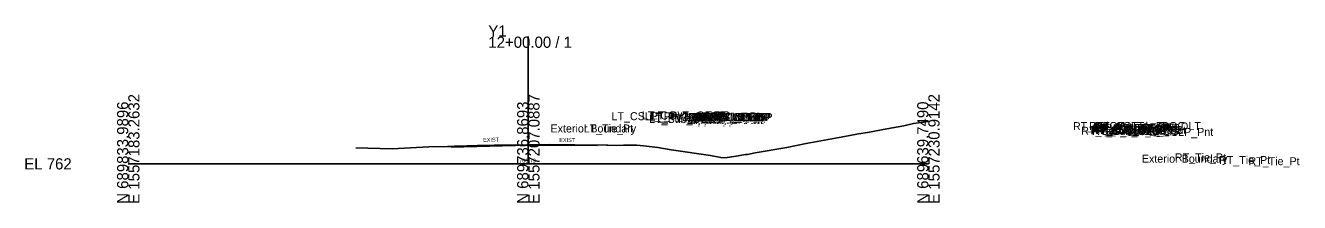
# Model space of a CAD drawing. Extents: x -26 to 303, y -10 to 5005.
# Drawn here: x -25.7 to 292.8, y 1990.3 to 2034.7 of the extents above; entities that cross this region are included whole.
import ezdxf

# ---------------------------------------------------------------- set-up
doc = ezdxf.new("R2010")
doc.units = 0
for name, color, linetype in [('Default', 7, 'Continuous'), ('Exist Cross Section Cell', 7, 'Continuous'), ('Exist XS Center Line Elevation Label', 7, 'Continuous'), ('Exist XS Ground Line', 7, 'Continuous'), ('Prop CMT Pvmt Course 1', 7, 'Continuous'), ('Prop CMT Pvmt Surface', 7, 'Continuous'), ('Prop XS SE Text', 7, 'Continuous')]:
    doc.layers.add(name, color=color, linetype=linetype)

msp = doc.modelspace()

# ---------------------------------------------------------------- linework, layer by layer
at = {"layer": 'Exist Cross Section Cell'}
for p, q in [((100, 2000), (100, 2031.86)), ((0, 2000), (100, 2000)), ((100, 2000), (200, 2000))]:
    msp.add_line(p, q, dxfattribs=at)
at = {"layer": 'Exist XS Ground Line'}
msp.add_lwpolyline([(56.85, 2003.98), (65.96, 2003.78), (75.1, 2004.22), (79.8, 2004.31), (80.39, 2004.31), (80.75, 2004.33), (81.54, 2004.42), (83.18, 2004.46), (83.69, 2004.47), (84.67, 2004.49), (85.59, 2004.52), (87.3, 2004.56), (91.45, 2004.65), (93.01, 2004.69), (94.36, 2004.71), (100, 2004.79), (105.33, 2004.86), (111.61, 2004.76), (119.57, 2004.66), (119.87, 2004.65), (122.02, 2004.63), (123.79, 2004.64), (127.09, 2004.72), (128.79, 2004.54), (132.4, 2004.13), (135.74, 2003.47), (145.55, 2002.05), (148.14, 2001.63), (149.12, 2001.48), (151.98, 2001.95), (154.26, 2002.33), (154.76, 2002.37), (156.71, 2002.75), (164.58, 2004.06), (169.43, 2005.08), (178.61, 2006.78), (182.51, 2007.5), (184.75, 2007.86), (189.65, 2008.78), (193.85, 2009.55), (196.32, 2010.07), (200, 2010.62)], dxfattribs=at)
at = {"layer": 'Prop CMT Pvmt Course 1'}
for p, q in [((80.75, 2004.21), (100, 2004.66)), ((80.75, 2004.33), (80.75, 2004.21)), ((100, 2004.66), (117.33, 2004.56)), ((117.33, 2004.69), (117.33, 2004.56))]:
    msp.add_line(p, q, dxfattribs=at)
for points in [[(100, 2004.79), (100, 2004.66)], [(100, 2004.66), (100, 2004.79)], [(100, 2004.79), (117.33, 2004.69)]]:
    msp.add_lwpolyline(points, dxfattribs=at)
at = {"layer": 'Prop CMT Pvmt Surface'}
msp.add_line((80.75, 2004.33), (100, 2004.79), dxfattribs=at)
msp.add_lwpolyline([(100, 2004.79), (117.33, 2004.69)], dxfattribs=at)

# ---------------------------------------------------------------- texts
at = {"layer": 'Default'}
for s, height, p in [('LT_CSLP_Pnt', 2, (120.8, 2010.93)), ('LT_CG_Top_BOC', 2, (128.4, 2011.12)), ('LT_PV2_OEOT', 2, (130.29, 2010.87)), ('LT_PV1_OEOT', 2, (130.86, 2011.12)), ('RT_PV1_OEEOP', 2, (139.94, 2010.72)), ('LT_PV1_OEEOP', 2, (139.98, 2010.72)), ('RT_PV1_IEEOP', 2, (140.58, 2010.72)), ('LT_PV1_IEEOP', 2, (140.63, 2010.72)), ('RT_PV1_PGL', 2, (141.84, 2010.85)), ('LT_PV1_PGL', 2, (141.89, 2010.85)), ('Exterior Boundary', 2, (105.55, 2007.86)), ('LT_Tie_Pt', 2, (113.85, 2007.86)), ('LT_Sub_OEOT', 2, (130.2, 2010.25)), ('LT_PV3_OEOT', 2, (130.29, 2010.62)), ('RT_Sub_OEEOP', 2, (139.27, 2009.97)), ('LT_Sub_OEEOP', 2, (139.32, 2009.97)), ('RT_PV2_OEEOP', 2, (139.37, 2010.6)), ('RT_PV3_OEEOP', 2, (139.37, 2010.35)), ('LT_PV2_OEEOP', 2, (139.42, 2010.6)), ('LT_PV3_OEEOP', 2, (139.42, 2010.35)), ('RT_PV2_IEEOP', 2, (140.01, 2010.6)), ('LT_PV2_IEEOP', 2, (140.06, 2010.6)), ('RT_PV2_PGL', 2, (141.27, 2010.6)), ('LT_PV2_PGL', 2, (141.32, 2010.6)), ('RT_Sub_Trench_Out_DLT', 2, (236.15, 2008.44)), ('RT_CG_Top_Face', 2, (240.19, 2008.47)), ('RT_CG1_Shelf_Out', 2, (240.53, 2007.45)), ('RT_CG_Bot_IE', 2, (240.76, 2007.52)), ('RT_PV2_OEOT', 2, (241.02, 2007.86)), ('RT_PV3_OEOT', 2, (241.02, 2007.61)), ('RT_CG_Top_Gut', 2, (241.17, 2007.97)), ('RT_PV1_OEOT', 2, (241.59, 2008.11)), ('RT_CG_Top_BOC', 2, (241.74, 2008.47)), ('RT_Sub_OEOT_CG', 2, (238.22, 2007.27)), ('RT_Sub_OEOT', 2, (240.93, 2007.23)), ('RT_CG_Bot_BOC', 2, (241.77, 2007.46)), ('RT_Sub_OEOP', 2, (244.36, 2007.19)), ('CSLP_Pnt', 2, (258.71, 2007)), ('-', 0.0001, (0, 2000)), ('Exterior Boundary', 2, (253.36, 2000.29)), ('RT_Tie_Pt', 2, (261.62, 2000.62)), ('RT_Tie_Pt', 2, (272.66, 1999.97)), ('RT_Tie_Pt', 2, (280.01, 1999.67))]:
    msp.add_text(s, height=height, dxfattribs=at).set_placement(p)
at = {"layer": 'Exist Cross Section Cell'}
for s, p in [('Y1', (90, 2031.86)), ('12+00.00 / 1', (90, 2029.06)), ('EL 762', (-26, 1998.6))]:
    msp.add_text(s, height=2.8, dxfattribs=at).set_placement(p)
for s, p in [('E 1557183.2632', (2.8, 1990)), ('E 1557207.0887', (102.8, 1990)), ('E 1557230.9142', (202.8, 1990)), ('N 689833.9896', (0, 1990)), ('N 689736.8693', (100, 1990)), ('N 689639.7490', (200, 1990))]:
    msp.add_text(s, height=2.8, rotation=90, dxfattribs=at).set_placement(p)
at = {"layer": 'Exist XS Center Line Elevation Label'}
msp.add_text('766.79', height=1, dxfattribs=at).set_placement((97.7, 2000.29))
at = {"layer": 'Prop XS SE Text'}
for rotation, p in [(1.0074, (88.7, 2005.49)), (359.6691, (107.72, 2005.47))]:
    msp.add_text('EXIST', height=1, rotation=rotation, dxfattribs=at).set_placement(p)

doc.saveas('drawing.dxf')
